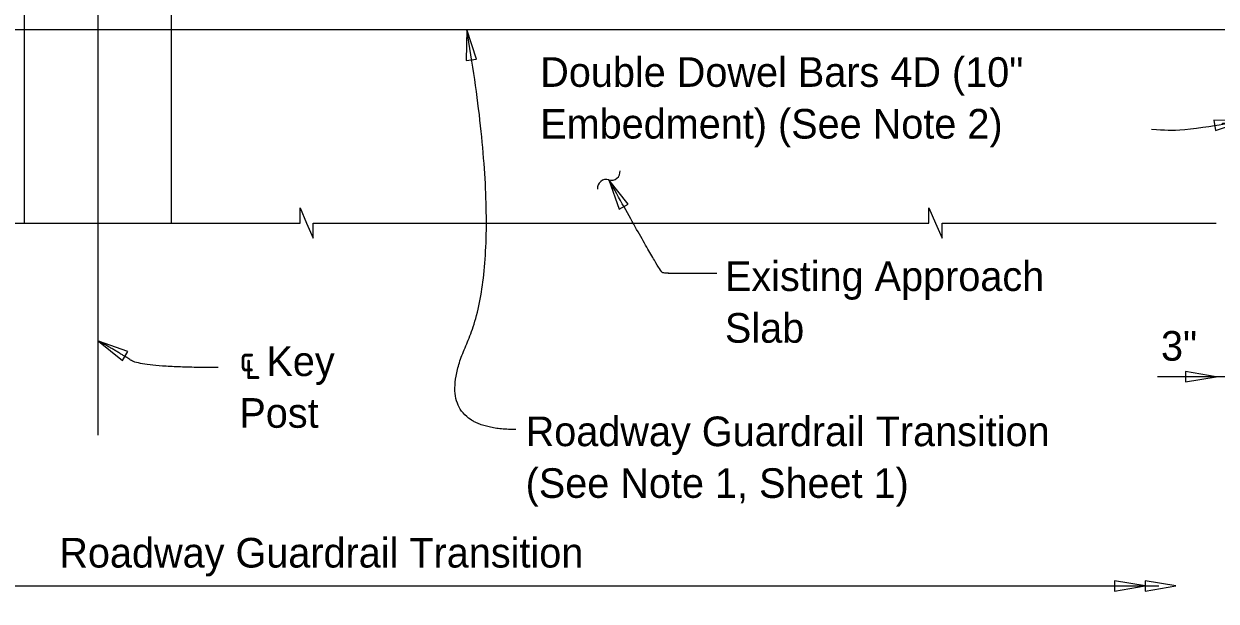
# Model space of a CAD drawing. Extents: x 21526.6 to 21598.7, y 56118.9 to 56155.9.
# Drawn here: x 21554.3 to 21562.41, y 56142.68 to 56146.61 of the extents above; entities that cross this region are included whole.
import ezdxf

# ---------------------------------------------------------------- set-up
doc = ezdxf.new("R2010")
doc.units = 0
for name, color, linetype in [('AdhocPoint_dp', 7, 'Continuous'), ('Border', 7, 'Continuous'), ('PlotBorder_dp', 7, 'Continuous'), ('SheetBorder_dp', 7, 'Continuous')]:
    doc.layers.add(name, color=color, linetype=linetype)

msp = doc.modelspace()

# ---------------------------------------------------------------- linework, layer by layer
at = {"layer": 'AdhocPoint_dp'}
for p, q in [((21554.3018, 56145.2536), (21554.3018, 56149.7195)), ((21555.3018, 56145.2536), (21555.3018, 56147.2315))]:
    msp.add_line(p, q, dxfattribs=at)
at = {"layer": 'PlotBorder_dp'}
for p, q in [((21554.8018, 56147.4803), (21554.8018, 56143.8094)), ((21565.892, 56144.2072), (21562.0129, 56144.2072))]:
    msp.add_line(p, q, dxfattribs=at)
for points in [[(21557.3129, 56146.5703), (21557.3084, 56146.3591), (21557.3782, 56146.3694)], [(21562.6076, 56145.9501), (21562.3964, 56145.9541), (21562.4069, 56145.8843)], [(21558.2791, 56145.5479), (21558.3496, 56145.3488), (21558.4112, 56145.3831)], [(21554.8059, 56144.4508), (21554.9698, 56144.3175), (21555.0045, 56144.379)], [(21562.4118, 56144.2072), (21562.2036, 56144.2425), (21562.2036, 56144.1719)], [(21561.9289, 56142.7836), (21561.7207, 56142.8189), (21561.7207, 56142.7483)], [(21562.1372, 56142.7836), (21561.9289, 56142.8189), (21561.9289, 56142.7483)]]:
    msp.add_lwpolyline(points, close=True, dxfattribs=at)
for points in [[(21554.1818, 56145.2536), (21556.1773, 56145.2536), (21556.1773, 56145.3569), (21556.2223, 56145.2536), (21556.2673, 56145.1503), (21556.2673, 56145.2536), (21558.1321, 56145.2536)], [(21558.1321, 56145.2536), (21560.457, 56145.2536), (21560.457, 56145.3569), (21560.502, 56145.2536), (21560.547, 56145.1503), (21560.547, 56145.2536), (21562.4118, 56145.2536)], [(21546.0419, 56142.7836), (21549.8888, 56142.7836), (21549.8888, 56142.8869), (21549.9338, 56142.7836), (21549.9788, 56142.6803), (21549.9788, 56142.7836), (21562.0226, 56142.7836)]]:
    msp.add_lwpolyline(points, dxfattribs=at)
for centre, start, end in [((21558.2614, 56145.4904), 73.27971, 185.00693), ((21558.2957, 56145.6046), 253.27971, 5.00693)]:
    msp.add_arc(centre, 0.0596, start, end, dxfattribs=at)
for points, degree in [([(21557.6456, 56143.8481), (21557.0476, 56143.8481), (21557.578, 56145.0202), (21557.3128, 56146.5703)], 2), ([(21561.9718, 56145.8919), (21562.0665, 56145.8883), (21562.1368, 56145.8743), (21562.6076, 56145.9501), (21562.2488, 56145.9047), (21563.2593, 56146.015), (21564.981, 56146.272)], 3), ([(21559.0141, 56144.9112), (21558.6601, 56144.9062), (21558.6254, 56144.9257), (21558.2792, 56145.5479)], 2), ([(21555.621, 56144.2694), (21555.1003, 56144.271), (21554.9516, 56144.3684), (21554.8059, 56144.4507)], 2)]:
    msp.add_open_spline(points, degree=degree, dxfattribs=at)
at = {"layer": 'SheetBorder_dp'}
msp.add_line((21552.8484, 56146.5703), (21566.2337, 56146.5703), dxfattribs=at)

# ---------------------------------------------------------------- texts
at = {"layer": 'Border'}
for s, p in [('3"', (21562.0364, 56144.317)), ('℄ Key ', (21555.7643, 56144.2123)), ('Post', (21555.7643, 56143.8603))]:
    msp.add_text(s, height=0.2016, dxfattribs=at).set_placement(p)
at = {"layer": 'PlotBorder_dp'}
for s, p in [('Double Dowel Bars 4D (10"', (21557.8119, 56146.1805)), ('Embedment) (See Note 2)', (21557.8119, 56145.8285)), ('Existing Approach ', (21559.0689, 56144.7912)), ('Slab', (21559.0689, 56144.4392)), ('Roadway Guardrail Transition', (21557.7125, 56143.7351)), ('(See Note 1, Sheet 1)', (21557.7125, 56143.3831)), ('Roadway Guardrail Transition', (21554.539, 56142.909))]:
    msp.add_text(s, height=0.2016, dxfattribs=at).set_placement(p)

doc.saveas('drawing.dxf')
